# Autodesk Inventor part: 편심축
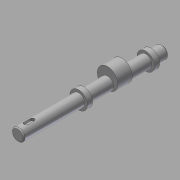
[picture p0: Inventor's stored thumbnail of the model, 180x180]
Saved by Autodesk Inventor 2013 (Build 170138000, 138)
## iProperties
Created: 2016-02
Part Number: 편심축
Material: 강철, 연강
Document SubType Name: Modeling
Designer: mduedu
Density: 1 g/cm^3
Author: mduedu
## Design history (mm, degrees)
sketch "스케치1"
  geometry: C1 r 6 at (0, 0); 1 further point
  constraints: 1 centre point, 1 coincident
  dimensions: "d0" = 12 diameter of C1
extrude "돌출1" new body sketch "스케치1" distance "d1" = 140; taper "d2" = 0 deg
chamfer "모따기1" distance "d3" = 1; stored, may be unused: second distance "d4" = 2, angle "d5" = 45 deg
node "작업 평면1"
sketch "스케치2"
  geometry: C1 r 10 at (0, 4); C2 r 6 at (0, 0) reference; 1 further point
  constraints: 1 centre point, 1 tangent, 1 vertical alignment
  dimensions: "d7" = 20 diameter of C1
extrude "돌출2" join sketch "스케치2" stored distance "d8" = 14; taper "d9" = 0 deg
node "작업 평면2"
sketch "스케치3"
  geometry: C1 r 8.5 at (0, 0); 1 further point
  constraints: 1 centre point, 1 coincident
  dimensions: "d12" = 17 diameter of C1
extrude "돌출3" join sketch "스케치3" distance "d13" = 5; taper "d14" = 0 deg
node "작업 평면3"
sketch "스케치4"
  geometry: L1 (-5, 140)-(5, 140) reference; L2 (0, 140)-(0, 0); L3 (-2, 132)-(-2, 126); L4 (2, 126)-(2, 132); A1 r 2 centre (0, 132) between (2, 132) and (-2, 132); A2 r 2 centre (0, 126) between (-2, 126) and (2, 126)
  constraints: 6 end point, 4 point on circle, 4 tangent, 2 centre point, 2 point on line, 1 midpoint, 1 parallel, 1 perpendicular
  dimensions: "d15" = 4 distance between parallel lines of L3 L4; "d17" = 6 distance edge to line of A1 L1; "d18" = 10 dimension on A2 A1
extrude "돌출4" cut sketch "스케치4" distance "d19" = 2.5; taper "d20" = 0 deg
sketch "스케치5"
  geometry: L1 (6, 53)-(6, 139) reference; L2 (-6, 53)-(-6, 139) reference; L3 (6, 115)-(-6, 115); L4 (-5, 140)-(5, 140) reference; L5 (6, 116.5)-(4.5, 115); L6 (6, 116.5)-(6, 115); L7 (4.5, 115)-(6, 115); 1 further point
  constraints: 8 end point, 4 point on line, 2 collinear, 1 perpendicular
  dimensions: "d21" = 25 distance between parallel lines of L3 L4; "d22" = 3 diameter of L5.start L3; "d24" = 45 deg angle of L3 L5
revolve "회전1" sketch "스케치5" stored, may be unused: angle "d25" = 90 deg
sketch "스케치6"
  geometry: L1 (6, 116.5)-(4.5, 115) reference; L2 (6, 113.5)-(4.5, 115) reference; 2 further points
  constraints: 1 coincident
node "작업 평면4"
sketch "스케치7"
  geometry: C1 r 8.5 at (0, -4); 1 further point
  constraints: 1 centre point, 1 coincident
  dimensions: "d27" = 17 diameter of C1
extrude "돌출5" join sketch "스케치7" distance "d29" = 5; taper "d30" = 0 deg
node "솔리드1"
other parameters: "d6" = -46, "d11" = -11, "d26" = 28
